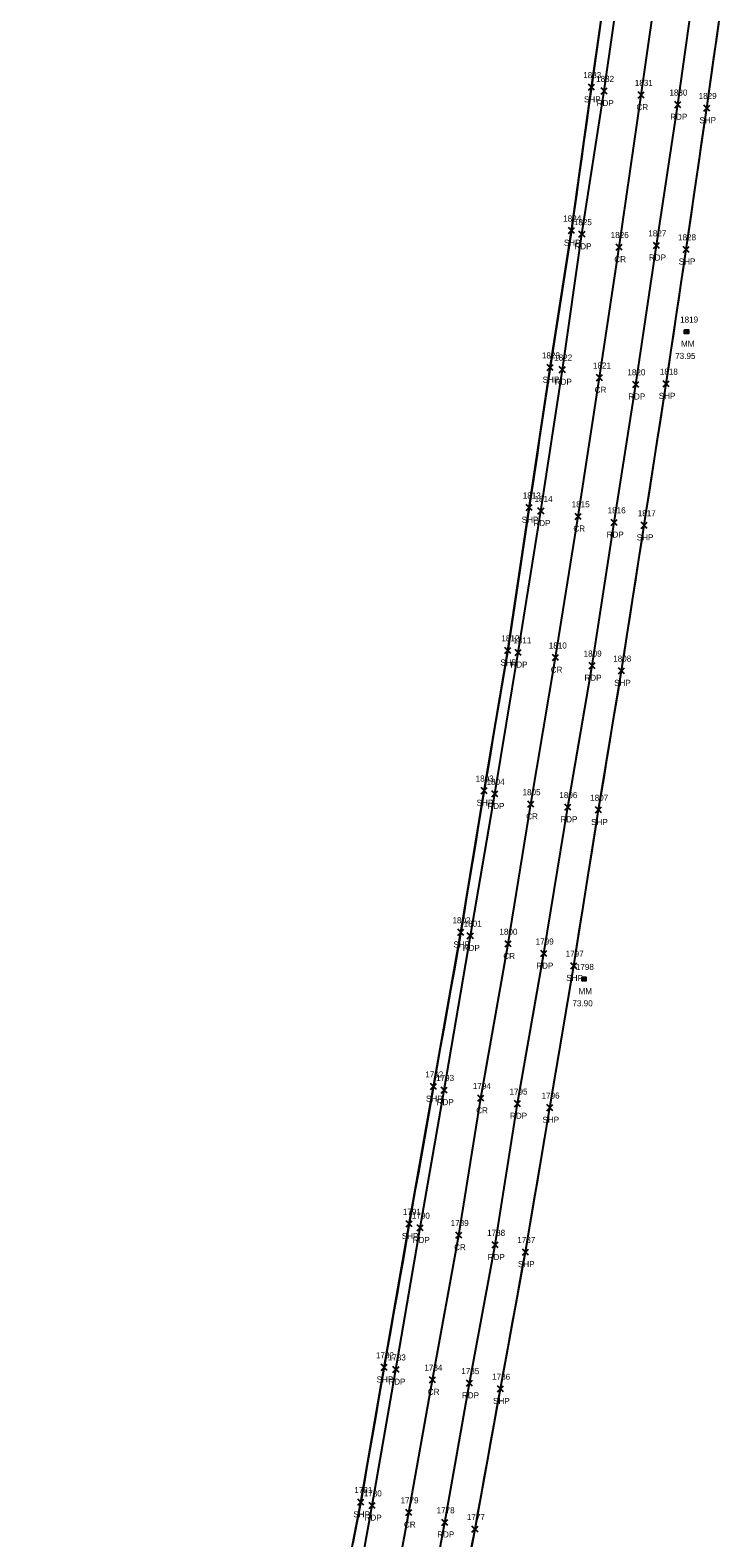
# Model space of a CAD drawing. Extents: x 1688195 to 1692013, y 424605 to 441234.
# Drawn here: x 1690311.5 to 1690541.4, y 434639.3 to 435137.4 of the extents above; entities that cross this region are included whole.
import ezdxf

# ---------------------------------------------------------------- set-up
doc = ezdxf.new("R2010")
doc.units = 0
for name, color, linetype in [('LSOGP', 7, 'Continuous'), ('P_A', 7, 'Continuous'), ('P_I', 7, 'Continuous'), ('P_TIC', 7, 'Continuous'), ('PET', 7, 'Continuous'), ('PRC', 7, 'Continuous'), ('PSP', 7, 'Continuous'), ('S_A', 7, 'Continuous'), ('S_C', 7, 'Continuous'), ('S_I', 7, 'Continuous'), ('SRM', 7, 'Continuous')]:
    doc.layers.add(name, color=color, linetype=linetype)

msp = doc.modelspace()

# ---------------------------------------------------------------- linework, layer by layer
at = {"layer": 'LSOGP'}
for points in [[(1690500.1, 435140.51), (1690499.32, 435135.03), (1690498.53, 435129.55), (1690497.74, 435124.07), (1690496.95, 435118.58), (1690496.13, 435112.66), (1690495.3, 435106.74), (1690494.47, 435100.81), (1690493.64, 435094.89), (1690492.81, 435088.97), (1690491.98, 435083.04), (1690491.15, 435077.12), (1690490.33, 435071.2), (1690489.45, 435065.54), (1690488.57, 435059.89), (1690487.69, 435054.23), (1690486.81, 435048.58), (1690485.93, 435042.92), (1690485.05, 435037.27), (1690484.17, 435031.61), (1690483.29, 435025.96), (1690482.43, 435020.17), (1690481.57, 435014.39), (1690480.7, 435008.61), (1690479.84, 435002.82), (1690478.98, 434997.04), (1690478.12, 434991.26), (1690477.26, 434985.47), (1690476.39, 434979.69), (1690475.51, 434973.79), (1690474.63, 434967.89), (1690473.75, 434962), (1690472.87, 434956.1), (1690471.99, 434950.2), (1690471.11, 434944.3), (1690470.23, 434938.41), (1690469.34, 434932.51), (1690468.36, 434926.72), (1690467.38, 434920.93), (1690466.4, 434915.13), (1690465.41, 434909.34), (1690464.43, 434903.55), (1690463.45, 434897.76), (1690462.46, 434891.97), (1690461.48, 434886.18), (1690460.52, 434880.33), (1690459.57, 434874.48), (1690458.61, 434868.62), (1690457.65, 434862.77), (1690456.7, 434856.92), (1690455.74, 434851.07), (1690454.78, 434845.22), (1690453.82, 434839.37), (1690452.69, 434833), (1690451.56, 434826.63), (1690450.43, 434820.26), (1690449.3, 434813.9), (1690448.16, 434807.53), (1690447.03, 434801.16), (1690445.9, 434794.79), (1690444.77, 434788.42), (1690443.77, 434782.75), (1690442.77, 434777.07), (1690441.78, 434771.4), (1690440.78, 434765.72), (1690439.78, 434760.05), (1690438.78, 434754.38), (1690437.79, 434748.7), (1690436.79, 434743.03), (1690435.75, 434737.11), (1690434.71, 434731.18), (1690433.67, 434725.26), (1690432.63, 434719.34), (1690431.59, 434713.42), (1690430.55, 434707.5), (1690429.51, 434701.58), (1690428.47, 434695.66), (1690427.5, 434690.09), (1690426.54, 434684.52), (1690425.58, 434678.95), (1690424.62, 434673.38), (1690423.65, 434667.81), (1690422.69, 434662.24), (1690421.73, 434656.67), (1690420.77, 434651.11), (1690419.46, 434644.36), (1690418.16, 434637.61)], [(1690457.28, 434635.64), (1690458.5, 434642.18), (1690459.55, 434647.98), (1690460.61, 434653.77), (1690461.66, 434659.57), (1690462.71, 434665.36), (1690463.76, 434671.16), (1690464.82, 434676.96), (1690465.87, 434682.75), (1690466.92, 434688.55), (1690467.95, 434694.2), (1690468.98, 434699.85), (1690470.01, 434705.5), (1690471.04, 434711.15), (1690472.07, 434716.8), (1690473.1, 434722.45), (1690474.13, 434728.1), (1690475.16, 434733.75), (1690476.17, 434739.71), (1690477.18, 434745.67), (1690478.19, 434751.64), (1690479.2, 434757.6), (1690480.21, 434763.56), (1690481.21, 434769.52), (1690482.22, 434775.48), (1690483.23, 434781.44), (1690484.22, 434787.3), (1690485.21, 434793.16), (1690486.19, 434799.02), (1690487.18, 434804.88), (1690488.17, 434810.74), (1690489.15, 434816.6), (1690490.14, 434822.46), (1690491.13, 434828.32), (1690492.15, 434834.75), (1690493.18, 434841.19), (1690494.2, 434847.63), (1690495.23, 434854.07), (1690496.25, 434860.5), (1690497.28, 434866.94), (1690498.3, 434873.38), (1690499.32, 434879.82), (1690500.28, 434885.57), (1690501.23, 434891.31), (1690502.18, 434897.06), (1690503.13, 434902.81), (1690504.08, 434908.56), (1690505.03, 434914.3), (1690505.98, 434920.05), (1690506.93, 434925.8), (1690507.86, 434931.8), (1690508.79, 434937.81), (1690509.73, 434943.82), (1690510.66, 434949.82), (1690511.59, 434955.83), (1690512.52, 434961.83), (1690513.46, 434967.84), (1690514.39, 434973.84), (1690515.3, 434979.69), (1690516.21, 434985.53), (1690517.12, 434991.38), (1690518.03, 434997.22), (1690518.94, 435003.07), (1690519.86, 435008.92), (1690520.77, 435014.76), (1690521.68, 435020.61), (1690522.5, 435026.16), (1690523.32, 435031.71), (1690524.15, 435037.25), (1690524.97, 435042.8), (1690525.79, 435048.35), (1690526.62, 435053.9), (1690527.44, 435059.45), (1690528.27, 435065), (1690529.12, 435070.84), (1690529.97, 435076.67), (1690530.82, 435082.51), (1690531.67, 435088.35), (1690532.52, 435094.18), (1690533.37, 435100.02), (1690534.23, 435105.85), (1690535.08, 435111.69), (1690535.86, 435117.26), (1690536.65, 435122.83), (1690537.43, 435128.41), (1690538.22, 435133.98), (1690539.01, 435139.55)]]:
    msp.add_lwpolyline(points, dxfattribs=at)
at = {"layer": 'P_TIC'}
for points in [[(1690495.95, 435117.58), (1690497.95, 435119.58)], [(1690497.95, 435117.58), (1690495.95, 435119.58)], [(1690500.19, 435116.33), (1690502.19, 435118.33)], [(1690502.19, 435116.33), (1690500.19, 435118.33)], [(1690512.41, 435115), (1690514.41, 435117)], [(1690514.41, 435115), (1690512.41, 435117)], [(1690524.5, 435111.81), (1690526.5, 435113.81)], [(1690526.5, 435111.81), (1690524.5, 435113.81)], [(1690534.08, 435110.69), (1690536.08, 435112.69)], [(1690536.08, 435110.69), (1690534.08, 435112.69)], [(1690489.33, 435070.2), (1690491.33, 435072.2)], [(1690491.33, 435070.2), (1690489.33, 435072.2)], [(1690492.84, 435069), (1690494.84, 435071)], [(1690494.84, 435069), (1690492.84, 435071)], [(1690505.08, 435064.76), (1690507.08, 435066.76)], [(1690507.08, 435064.76), (1690505.08, 435066.76)], [(1690517.45, 435065.31), (1690519.45, 435067.31)], [(1690519.45, 435065.31), (1690517.45, 435067.31)], [(1690527.27, 435064), (1690529.27, 435066)], [(1690529.27, 435064), (1690527.27, 435066)], [(1690482.29, 435024.96), (1690484.29, 435026.96)], [(1690484.29, 435024.96), (1690482.29, 435026.96)], [(1690486.35, 435024.26), (1690488.35, 435026.26)], [(1690488.35, 435024.26), (1690486.35, 435026.26)], [(1690498.59, 435021.62), (1690500.59, 435023.62)], [(1690500.59, 435021.62), (1690498.59, 435023.62)], [(1690510.62, 435019.4), (1690512.62, 435021.4)], [(1690512.62, 435019.4), (1690510.62, 435021.4)], [(1690520.68, 435019.61), (1690522.68, 435021.61)], [(1690522.68, 435019.61), (1690520.68, 435021.61)], [(1690475.39, 434978.69), (1690477.39, 434980.69)], [(1690477.39, 434978.69), (1690475.39, 434980.69)], [(1690479.29, 434977.56), (1690481.29, 434979.56)], [(1690481.29, 434977.56), (1690479.29, 434979.56)], [(1690491.56, 434975.79), (1690493.56, 434977.79)], [(1690493.56, 434975.79), (1690491.56, 434977.79)], [(1690503.49, 434973.79), (1690505.49, 434975.79)], [(1690505.49, 434973.79), (1690503.49, 434975.79)], [(1690513.39, 434972.84), (1690515.39, 434974.84)], [(1690515.39, 434972.84), (1690513.39, 434974.84)], [(1690468.34, 434931.51), (1690470.34, 434933.51)], [(1690470.34, 434931.51), (1690468.34, 434933.51)], [(1690471.72, 434930.84), (1690473.72, 434932.84)], [(1690473.72, 434930.84), (1690471.72, 434932.84)], [(1690484.08, 434929.13), (1690486.08, 434931.13)], [(1690486.08, 434929.13), (1690484.08, 434931.13)], [(1690496.16, 434926.47), (1690498.16, 434928.47)], [(1690498.16, 434926.47), (1690496.16, 434928.47)], [(1690505.93, 434924.8), (1690507.93, 434926.8)], [(1690507.93, 434924.8), (1690505.93, 434926.8)], [(1690460.48, 434885.18), (1690462.48, 434887.18)], [(1690462.48, 434885.18), (1690460.48, 434887.18)], [(1690464.09, 434884.09), (1690466.09, 434886.09)], [(1690466.09, 434884.09), (1690464.09, 434886.09)], [(1690475.98, 434880.67), (1690477.98, 434882.67)], [(1690477.98, 434880.67), (1690475.98, 434882.67)], [(1690488.19, 434879.71), (1690490.19, 434881.71)], [(1690490.19, 434879.71), (1690488.19, 434881.71)], [(1690498.32, 434878.82), (1690500.32, 434880.82)], [(1690500.32, 434878.82), (1690498.32, 434880.82)], [(1690452.82, 434838.37), (1690454.82, 434840.37)], [(1690454.82, 434838.37), (1690452.82, 434840.37)], [(1690455.96, 434837.24), (1690457.96, 434839.24)], [(1690457.96, 434837.24), (1690455.96, 434839.24)], [(1690468.42, 434834.55), (1690470.42, 434836.55)], [(1690470.42, 434834.55), (1690468.42, 434836.55)], [(1690480.24, 434831.34), (1690482.24, 434833.34)], [(1690482.24, 434831.34), (1690480.24, 434833.34)], [(1690490.13, 434827.32), (1690492.13, 434829.32)], [(1690492.13, 434827.32), (1690490.13, 434829.32)], [(1690443.77, 434787.42), (1690445.77, 434789.42)], [(1690445.77, 434787.42), (1690443.77, 434789.42)], [(1690447.33, 434786.27), (1690449.33, 434788.27)], [(1690449.33, 434786.27), (1690447.33, 434788.27)], [(1690459.46, 434783.56), (1690461.46, 434785.56)], [(1690461.46, 434783.56), (1690459.46, 434785.56)], [(1690471.58, 434781.77), (1690473.58, 434783.77)], [(1690473.58, 434781.77), (1690471.58, 434783.77)], [(1690482.23, 434780.44), (1690484.23, 434782.44)], [(1690484.23, 434780.44), (1690482.23, 434782.44)], [(1690435.79, 434742.03), (1690437.79, 434744.03)], [(1690437.79, 434742.03), (1690435.79, 434744.03)], [(1690439.42, 434740.74), (1690441.42, 434742.74)], [(1690441.42, 434740.74), (1690439.42, 434742.74)], [(1690452.16, 434738.34), (1690454.16, 434740.34)], [(1690454.16, 434738.34), (1690452.16, 434740.34)], [(1690464.19, 434735.09), (1690466.19, 434737.09)], [(1690466.19, 434735.09), (1690464.19, 434737.09)], [(1690474.16, 434732.75), (1690476.16, 434734.75)], [(1690476.16, 434732.75), (1690474.16, 434734.75)], [(1690427.47, 434694.66), (1690429.47, 434696.66)], [(1690429.47, 434694.66), (1690427.47, 434696.66)], [(1690431.39, 434693.93), (1690433.39, 434695.93)], [(1690433.39, 434693.93), (1690431.39, 434695.93)], [(1690443.47, 434690.57), (1690445.47, 434692.57)], [(1690445.47, 434690.57), (1690443.47, 434692.57)], [(1690455.68, 434689.41), (1690457.68, 434691.41)], [(1690457.68, 434689.41), (1690455.68, 434691.41)], [(1690465.92, 434687.55), (1690467.92, 434689.55)], [(1690467.92, 434687.55), (1690465.92, 434689.55)], [(1690419.77, 434650.11), (1690421.77, 434652.11)], [(1690421.77, 434650.11), (1690419.77, 434652.11)], [(1690423.53, 434649), (1690425.53, 434651)], [(1690425.53, 434649), (1690423.53, 434651)], [(1690435.6, 434646.71), (1690437.6, 434648.71)], [(1690437.6, 434646.71), (1690435.6, 434648.71)], [(1690447.51, 434643.44), (1690449.51, 434645.44)], [(1690449.51, 434643.44), (1690447.51, 434645.44)], [(1690457.5, 434641.18), (1690459.5, 434643.18)], [(1690459.5, 434641.18), (1690457.5, 434643.18)]]:
    msp.add_lwpolyline(points, dxfattribs=at)
at = {"layer": 'PET'}
for points in [[(1690315.83, 434126.81), (1690327.01, 434174.5), (1690337.93, 434222.04), (1690348.05, 434267), (1690358.4, 434314.01), (1690368.68, 434362.2), (1690378.11, 434407.82), (1690386.43, 434449.01), (1690396.48, 434499.66), (1690405.96, 434548.92), (1690414.68, 434595.69), (1690424.53, 434650), (1690432.39, 434694.93), (1690440.42, 434741.74), (1690448.33, 434787.27), (1690456.96, 434838.24), (1690465.09, 434885.09), (1690472.72, 434931.84), (1690480.29, 434978.56), (1690487.35, 435025.26), (1690493.84, 435070), (1690501.19, 435117.33), (1690507.41, 435161.22)], [(1690339.32, 434119.7), (1690350.76, 434169.07), (1690361.62, 434215.61), (1690372, 434262), (1690382.17, 434309.37), (1690392.66, 434356.77), (1690402.21, 434401.95), (1690410.95, 434444.74), (1690420.58, 434495.83), (1690429.7, 434542.74), (1690438.71, 434591.72), (1690448.51, 434644.44), (1690456.68, 434690.41), (1690465.19, 434736.09), (1690472.58, 434782.77), (1690481.24, 434832.34), (1690489.19, 434880.71), (1690497.16, 434927.47), (1690504.49, 434974.79), (1690511.62, 435020.4), (1690518.45, 435066.31), (1690525.5, 435112.81), (1690531.76, 435157.71)]]:
    msp.add_lwpolyline(points, dxfattribs=at)
at = {"layer": 'PRC'}
msp.add_lwpolyline([(1690327.68, 434123), (1690339.72, 434172), (1690348.89, 434218.79), (1690360.52, 434264.84), (1690370.29, 434311.69), (1690380.26, 434359.53), (1690389.89, 434404.53), (1690398.18, 434447.2), (1690408.85, 434497.53), (1690418, 434545.9), (1690426.75, 434593.69), (1690436.6, 434647.71), (1690444.47, 434691.57), (1690453.16, 434739.34), (1690460.46, 434784.56), (1690469.42, 434835.55), (1690476.98, 434881.67), (1690485.08, 434930.13), (1690492.56, 434976.79), (1690499.59, 435022.62), (1690506.08, 435065.76), (1690513.41, 435116), (1690519.53, 435159.11)], dxfattribs=at)
at = {"layer": 'PSP'}
for points in [[(1690311.54, 434127.65), (1690322.57, 434175.56), (1690333.52, 434223.19), (1690343.68, 434268.37), (1690353.9, 434314.97), (1690364.1, 434363.81), (1690373.51, 434408.67), (1690382.02, 434450.77), (1690391.83, 434500.04), (1690401.55, 434549.95), (1690410.34, 434597.12), (1690420.77, 434651.11), (1690428.47, 434695.66), (1690436.79, 434743.03), (1690444.77, 434788.42), (1690453.82, 434839.37), (1690461.48, 434886.18), (1690469.34, 434932.51), (1690476.39, 434979.69), (1690483.29, 435025.96), (1690490.33, 435071.2), (1690496.95, 435118.58), (1690503.25, 435162.44)], [(1690349.06, 434117.45), (1690361.33, 434170.48), (1690371.41, 434213.84), (1690381.66, 434259.36), (1690392.07, 434307.86), (1690401.83, 434354.04), (1690411.58, 434400.23), (1690420.15, 434442.11), (1690430.57, 434494.27), (1690439.34, 434540.85), (1690448.73, 434589.84), (1690458.5, 434642.18), (1690466.92, 434688.55), (1690475.16, 434733.75), (1690483.23, 434781.44), (1690491.13, 434828.32), (1690499.32, 434879.82), (1690506.93, 434925.8), (1690514.39, 434973.84), (1690521.68, 435020.61), (1690528.27, 435065), (1690535.08, 435111.69), (1690541.36, 435156.27)]]:
    msp.add_lwpolyline(points, dxfattribs=at)
at = {"layer": 'SRM'}
for points in [[(1690527.75, 435038.43), (1690529, 435038.43), (1690529, 435037.18), (1690527.75, 435037.18)], [(1690493.89, 434824.56), (1690495.14, 434824.56), (1690495.14, 434823.31), (1690493.89, 434823.31)]]:
    msp.add_lwpolyline(points, close=True, dxfattribs=at)
for centre in [(1690528.38, 435037.81), (1690494.52, 434823.94)]:
    msp.add_circle(centre, 0.0833, dxfattribs=at)

# ---------------------------------------------------------------- texts
at = {"layer": 'P_A'}
for s, p in [('SHP', (1690494.49, 435113.58)), ('RDP', (1690498.68, 435112.33)), ('CR', (1690511.84, 435111)), ('RDP', (1690522.98, 435107.81)), ('SHP', (1690532.61, 435106.69)), ('SHP', (1690487.86, 435066.2)), ('RDP', (1690491.33, 435065)), ('RDP', (1690515.94, 435061.31)), ('CR', (1690504.51, 435060.76)), ('SHP', (1690525.8, 435060)), ('SHP', (1690480.83, 435020.96)), ('RDP', (1690484.84, 435020.26)), ('CR', (1690498.03, 435017.62)), ('RDP', (1690509.1, 435015.4)), ('SHP', (1690519.21, 435015.61)), ('SHP', (1690473.93, 434974.69)), ('RDP', (1690477.78, 434973.56)), ('CR', (1690490.99, 434971.79)), ('RDP', (1690501.98, 434969.79)), ('SHP', (1690511.92, 434968.84)), ('SHP', (1690466.88, 434927.51)), ('RDP', (1690470.21, 434926.84)), ('CR', (1690483.51, 434925.13)), ('RDP', (1690494.65, 434922.47)), ('SHP', (1690504.46, 434920.8)), ('SHP', (1690459.02, 434881.18)), ('RDP', (1690462.58, 434880.09)), ('CR', (1690475.41, 434876.67)), ('RDP', (1690486.68, 434875.71)), ('SHP', (1690496.86, 434874.82)), ('SHP', (1690451.36, 434834.37)), ('RDP', (1690454.45, 434833.24)), ('CR', (1690467.85, 434830.55)), ('RDP', (1690478.73, 434827.34)), ('SHP', (1690488.66, 434823.32)), ('SHP', (1690442.3, 434783.42)), ('RDP', (1690445.82, 434782.27)), ('CR', (1690458.9, 434779.56)), ('RDP', (1690470.07, 434777.77)), ('SHP', (1690480.77, 434776.44)), ('SHP', (1690434.32, 434738.03)), ('RDP', (1690437.91, 434736.74)), ('CR', (1690451.59, 434734.34)), ('RDP', (1690462.68, 434731.09)), ('SHP', (1690472.69, 434728.75)), ('SHP', (1690426, 434690.66)), ('RDP', (1690429.88, 434689.93)), ('CR', (1690442.9, 434686.57)), ('RDP', (1690454.17, 434685.41)), ('SHP', (1690464.46, 434683.55)), ('SHP', (1690418.3, 434646.11)), ('RDP', (1690422.02, 434645)), ('CR', (1690435.03, 434642.71)), ('RDP', (1690446, 434639.44))]:
    msp.add_text(s, height=2, dxfattribs=at).set_placement(p)
at = {"layer": 'P_I'}
for s, p in [('1833', (1690494.26, 435121.58)), ('1832', (1690498.5, 435120.33)), ('1831', (1690511.28, 435119)), ('1830', (1690522.72, 435115.81)), ('1829', (1690532.38, 435114.69)), ('1824', (1690487.63, 435074.2)), ('1825', (1690491.15, 435073)), ('1826', (1690503.33, 435068.76)), ('1827', (1690515.76, 435069.31)), ('1828', (1690525.57, 435068)), ('1823', (1690480.6, 435028.96)), ('1822', (1690484.66, 435028.26)), ('1821', (1690497.47, 435025.62)), ('1820', (1690508.84, 435023.4)), ('1818', (1690519.55, 435023.61)), ('1813', (1690474.27, 434982.69)), ('1814', (1690478.16, 434981.56)), ('1815', (1690490.43, 434979.79)), ('1816', (1690502.31, 434977.79)), ('1817', (1690512.26, 434976.84)), ('1812', (1690467.22, 434935.51)), ('1811', (1690471.16, 434934.84)), ('1810', (1690482.87, 434933.13)), ('1809', (1690494.38, 434930.47)), ('1808', (1690504.16, 434928.8)), ('1803', (1690458.71, 434889.18)), ('1804', (1690462.32, 434888.09)), ('1805', (1690474.2, 434884.67)), ('1806', (1690486.36, 434883.71)), ('1807', (1690496.55, 434882.82)), ('1802', (1690451.05, 434842.37)), ('1801', (1690454.75, 434841.24)), ('1800', (1690466.56, 434838.55)), ('1799', (1690478.54, 434835.34)), ('1797', (1690488.44, 434831.32)), ('1792', (1690442.08, 434791.42)), ('1793', (1690445.64, 434790.27)), ('1794', (1690457.77, 434787.56)), ('1795', (1690469.89, 434785.77)), ('1796', (1690480.49, 434784.44)), ('1791', (1690434.66, 434746.03)), ('1790', (1690437.64, 434744.74)), ('1789', (1690450.46, 434742.34)), ('1788', (1690462.5, 434739.09)), ('1787', (1690472.47, 434736.75)), ('1782', (1690425.77, 434698.66)), ('1783', (1690429.69, 434697.93)), ('1784', (1690441.78, 434694.57)), ('1785', (1690453.98, 434693.41)), ('1786', (1690464.17, 434691.55)), ('1781', (1690418.64, 434654.11)), ('1780', (1690421.75, 434653)), ('1779', (1690433.9, 434650.71)), ('1778', (1690445.82, 434647.44)), ('1777', (1690455.81, 434645.18))]:
    msp.add_text(s, height=2, dxfattribs=at).set_placement(p)
at = {"layer": 'S_A'}
for p in [(1690526.57, 435032.81), (1690492.71, 434818.94)]:
    msp.add_text('MM', height=2, dxfattribs=at).set_placement(p)
at = {"layer": 'S_C'}
for s, p in [('73.95', (1690524.63, 435028.81)), ('73.90', (1690490.68, 434814.94))]:
    msp.add_text(s, height=2, dxfattribs=at).set_placement(p)
at = {"layer": 'S_I'}
for s, p in [('1819', (1690526.25, 435040.81)), ('1798', (1690491.82, 434826.94))]:
    msp.add_text(s, height=2, dxfattribs=at).set_placement(p)

doc.saveas('drawing.dxf')
